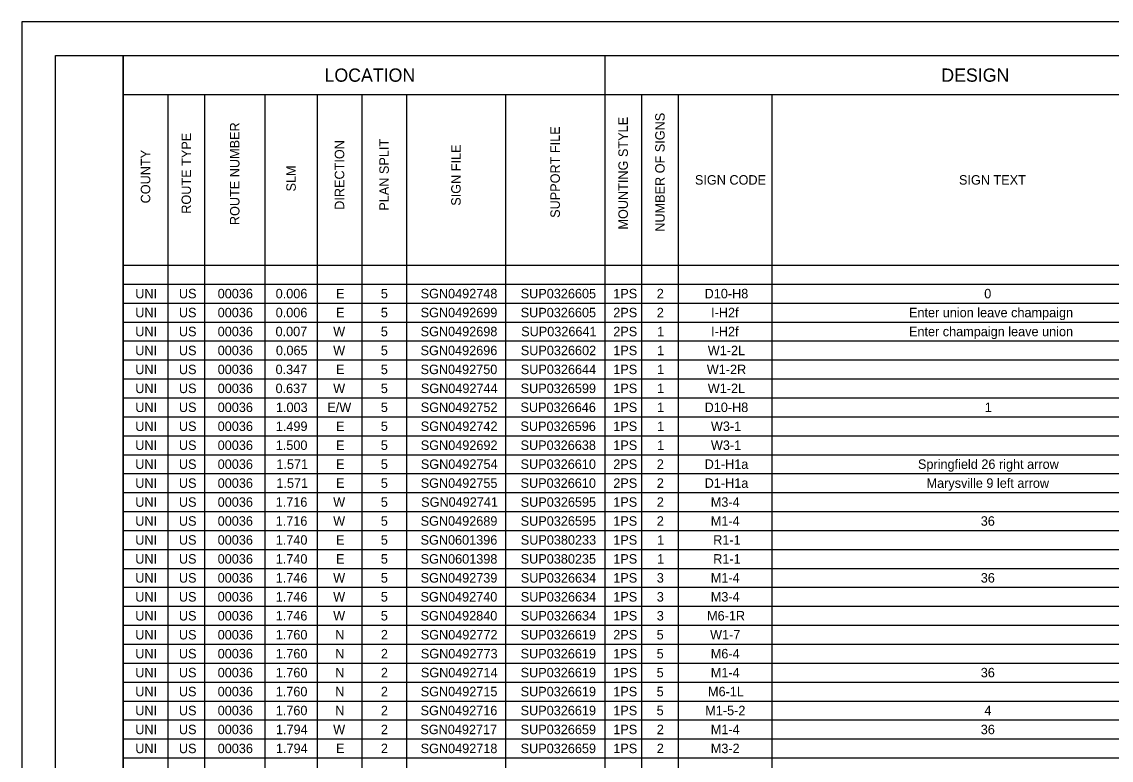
# Model space of a CAD drawing. Extents: x 0 to 34, y 0 to 22.
# Drawn here: x 0 to 16.1, y 11.09 to 22 of the extents above; entities that cross this region are included whole.
import ezdxf

# ---------------------------------------------------------------- set-up
doc = ezdxf.new("R2010")
doc.units = 0
for name, color, linetype in [('Default', 7, 'Continuous'), ('SH_Border', 7, 'Continuous'), ('SH_Cut_Line', 7, 'Continuous'), ('SH_Data', 7, 'Continuous')]:
    doc.layers.add(name, color=color, linetype=linetype)

msp = doc.modelspace()

# ---------------------------------------------------------------- linework, layer by layer
at = {"layer": 'SH_Border'}
for points in [[(0.5, 21.5), (1.5, 21.5), (1.5, 0.5), (0.5, 0.5)], [(1.5, 21.5), (33.5, 21.5), (33.5, 0.5), (1.5, 0.5)]]:
    msp.add_lwpolyline(points, close=True, dxfattribs=at)
at = {"layer": 'SH_Cut_Line'}
msp.add_lwpolyline([(0, 0), (34, 0), (34, 22), (0, 22)], close=True, dxfattribs=at)
at = {"layer": 'SH_Data'}
for p, q in [((1.5, 21.5), (32.004, 21.5)), ((8.615, 21.5), (8.615, 0.764)), ((1.5, 20.924), (28.232, 20.924)), ((1.5, 20.924), (1.5, 0.764)), ((2.159, 20.924), (2.159, 0.764)), ((2.702, 20.924), (2.702, 0.764)), ((3.592, 20.924), (3.592, 0.764)), ((4.366, 20.924), (4.366, 0.764)), ((5.025, 20.924), (5.025, 0.764)), ((5.684, 20.924), (5.684, 0.764)), ((7.149, 20.924), (7.149, 0.764)), ((9.159, 20.924), (9.159, 0.764)), ((9.702, 20.924), (9.702, 0.764)), ((11.086, 20.924), (11.086, 0.764)), ((1.5, 18.404), (32.004, 18.404)), ((1.5, 18.124), (32.004, 18.124)), ((1.5, 17.844), (32.004, 17.844)), ((1.5, 17.564), (32.004, 17.564)), ((1.5, 17.284), (32.004, 17.284)), ((1.5, 17.004), (32.004, 17.004)), ((1.5, 16.724), (32.004, 16.724)), ((1.5, 16.444), (32.004, 16.444)), ((1.5, 16.164), (32.004, 16.164)), ((1.5, 15.884), (32.004, 15.884)), ((1.5, 15.604), (32.004, 15.604)), ((1.5, 15.324), (32.004, 15.324)), ((1.5, 15.044), (32.004, 15.044)), ((1.5, 14.764), (32.004, 14.764)), ((1.5, 14.484), (32.004, 14.484)), ((1.5, 14.204), (32.004, 14.204)), ((1.5, 13.924), (32.004, 13.924)), ((1.5, 13.644), (32.004, 13.644)), ((1.5, 13.364), (32.004, 13.364)), ((1.5, 13.084), (32.004, 13.084)), ((1.5, 12.804), (32.004, 12.804)), ((1.5, 12.524), (32.004, 12.524)), ((1.5, 12.244), (32.004, 12.244)), ((1.5, 11.964), (32.004, 11.964)), ((1.5, 11.684), (32.004, 11.684)), ((1.5, 11.404), (32.004, 11.404)), ((1.5, 11.124), (32.004, 11.124))]:
    msp.add_line(p, q, dxfattribs=at)

# ---------------------------------------------------------------- texts
at = {"layer": 'Default'}
for s, height, p in [('LOCATION', 0.196, (4.474, 21.114)), ('DESIGN', 0.196, (13.589, 21.114)), ('SIGN CODE', 0.14, (9.948, 19.594)), ('SIGN TEXT', 0.14, (13.85, 19.594)), ('UNI', 0.14, (1.677, 17.914)), ('US', 0.14, (2.322, 17.914)), ('00036', 0.14, (2.895, 17.914)), ('0.006', 0.14, (3.752, 17.914)), ('E', 0.14, (4.645, 17.914)), ('5', 0.14, (5.306, 17.914)), ('SGN0492748', 0.14, (5.894, 17.914)), ('SUP0326605', 0.14, (7.373, 17.914)), ('1PS', 0.14, (8.741, 17.914)), ('2', 0.14, (9.384, 17.914)), ('D10-H8', 0.14, (10.091, 17.914)), ('0', 0.14, (14.223, 17.914)), ('UNI', 0.14, (1.677, 17.634)), ('US', 0.14, (2.322, 17.634)), ('00036', 0.14, (2.895, 17.634)), ('0.006', 0.14, (3.752, 17.634)), ('E', 0.14, (4.645, 17.634)), ('5', 0.14, (5.306, 17.634)), ('SGN0492699', 0.14, (5.894, 17.634)), ('SUP0326605', 0.14, (7.373, 17.634)), ('2PS', 0.14, (8.741, 17.634)), ('2', 0.14, (9.384, 17.634)), ('I-H2f', 0.14, (10.187, 17.634)), ('Enter union leave champaign', 0.14, (13.111, 17.634)), ('UNI', 0.14, (1.677, 17.354)), ('US', 0.14, (2.322, 17.354)), ('00036', 0.14, (2.895, 17.354)), ('0.007', 0.14, (3.75, 17.354)), ('W', 0.14, (4.602, 17.354)), ('5', 0.14, (5.306, 17.354)), ('SGN0492698', 0.14, (5.894, 17.354)), ('SUP0326641', 0.14, (7.38, 17.354)), ('2PS', 0.14, (8.741, 17.354)), ('1', 0.14, (9.389, 17.354)), ('I-H2f', 0.14, (10.187, 17.354)), ('Enter champaign leave union', 0.14, (13.111, 17.354)), ('UNI', 0.14, (1.677, 17.074)), ('US', 0.14, (2.322, 17.074)), ('00036', 0.14, (2.895, 17.074)), ('0.065', 0.14, (3.755, 17.074)), ('W', 0.14, (4.602, 17.074)), ('5', 0.14, (5.306, 17.074)), ('SGN0492696', 0.14, (5.893, 17.074)), ('SUP0326602', 0.14, (7.374, 17.074)), ('1PS', 0.14, (8.741, 17.074)), ('1', 0.14, (9.389, 17.074)), ('W1-2L', 0.14, (10.138, 17.074)), ('UNI', 0.14, (1.677, 16.794)), ('US', 0.14, (2.322, 16.794)), ('00036', 0.14, (2.895, 16.794)), ('0.347', 0.14, (3.75, 16.794)), ('E', 0.14, (4.645, 16.794)), ('5', 0.14, (5.306, 16.794)), ('SGN0492750', 0.14, (5.893, 16.794)), ('SUP0326644', 0.14, (7.374, 16.794)), ('1PS', 0.14, (8.741, 16.794)), ('1', 0.14, (9.389, 16.794)), ('W1-2R', 0.14, (10.123, 16.794)), ('UNI', 0.14, (1.677, 16.514)), ('US', 0.14, (2.322, 16.514)), ('00036', 0.14, (2.895, 16.514)), ('0.637', 0.14, (3.75, 16.514)), ('W', 0.14, (4.602, 16.514)), ('5', 0.14, (5.306, 16.514)), ('SGN0492744', 0.14, (5.897, 16.514)), ('SUP0326599', 0.14, (7.372, 16.514)), ('1PS', 0.14, (8.741, 16.514)), ('1', 0.14, (9.389, 16.514)), ('W1-2L', 0.14, (10.138, 16.514)), ('UNI', 0.14, (1.677, 16.234)), ('US', 0.14, (2.322, 16.234)), ('00036', 0.14, (2.895, 16.234)), ('1.003', 0.14, (3.756, 16.234)), ('E/W', 0.14, (4.515, 16.234)), ('5', 0.14, (5.306, 16.234)), ('SGN0492752', 0.14, (5.896, 16.234)), ('SUP0326646', 0.14, (7.37, 16.234)), ('1PS', 0.14, (8.741, 16.234)), ('1', 0.14, (9.389, 16.234)), ('D10-H8', 0.14, (10.091, 16.234)), ('1', 0.14, (14.232, 16.234)), ('UNI', 0.14, (1.677, 15.954)), ('US', 0.14, (2.322, 15.954)), ('00036', 0.14, (2.895, 15.954)), ('1.499', 0.14, (3.754, 15.954)), ('E', 0.14, (4.645, 15.954)), ('5', 0.14, (5.306, 15.954)), ('SGN0492742', 0.14, (5.896, 15.954)), ('SUP0326596', 0.14, (7.37, 15.954)), ('1PS', 0.14, (8.741, 15.954)), ('1', 0.14, (9.389, 15.954)), ('W3-1', 0.14, (10.184, 15.954)), ('UNI', 0.14, (1.677, 15.674)), ('US', 0.14, (2.322, 15.674)), ('00036', 0.14, (2.895, 15.674)), ('1.500', 0.14, (3.753, 15.674)), ('E', 0.14, (4.645, 15.674)), ('5', 0.14, (5.306, 15.674)), ('SGN0492692', 0.14, (5.896, 15.674)), ('SUP0326638', 0.14, (7.371, 15.674)), ('1PS', 0.14, (8.741, 15.674)), ('1', 0.14, (9.389, 15.674)), ('W3-1', 0.14, (10.184, 15.674)), ('UNI', 0.14, (1.677, 15.394)), ('US', 0.14, (2.322, 15.394)), ('00036', 0.14, (2.895, 15.394)), ('1.571', 0.14, (3.762, 15.394)), ('E', 0.14, (4.645, 15.394)), ('5', 0.14, (5.306, 15.394)), ('SGN0492754', 0.14, (5.897, 15.394)), ('SUP0326610', 0.14, (7.371, 15.394)), ('2PS', 0.14, (8.741, 15.394)), ('2', 0.14, (9.384, 15.394)), ('D1-H1a', 0.14, (10.092, 15.394)), ('Springfield 26 right arrow', 0.14, (13.244, 15.394)), ('UNI', 0.14, (1.677, 15.114)), ('US', 0.14, (2.322, 15.114)), ('00036', 0.14, (2.895, 15.114)), ('1.571', 0.14, (3.762, 15.114)), ('E', 0.14, (4.645, 15.114)), ('5', 0.14, (5.306, 15.114)), ('SGN0492755', 0.14, (5.895, 15.114)), ('SUP0326610', 0.14, (7.371, 15.114)), ('2PS', 0.14, (8.741, 15.114)), ('2', 0.14, (9.384, 15.114)), ('D1-H1a', 0.14, (10.092, 15.114)), ('Marysville 9 left arrow', 0.14, (13.371, 15.114)), ('UNI', 0.14, (1.677, 14.834)), ('US', 0.14, (2.322, 14.834)), ('00036', 0.14, (2.895, 14.834)), ('1.716', 0.14, (3.752, 14.834)), ('W', 0.14, (4.602, 14.834)), ('5', 0.14, (5.306, 14.834)), ('SGN0492741', 0.14, (5.902, 14.834)), ('SUP0326595', 0.14, (7.373, 14.834)), ('1PS', 0.14, (8.741, 14.834)), ('2', 0.14, (9.384, 14.834)), ('M3-4', 0.14, (10.182, 14.834)), ('UNI', 0.14, (1.677, 14.554)), ('US', 0.14, (2.322, 14.554)), ('00036', 0.14, (2.895, 14.554)), ('1.716', 0.14, (3.752, 14.554)), ('W', 0.14, (4.602, 14.554)), ('5', 0.14, (5.306, 14.554)), ('SGN0492689', 0.14, (5.894, 14.554)), ('SUP0326595', 0.14, (7.373, 14.554)), ('1PS', 0.14, (8.741, 14.554)), ('2', 0.14, (9.384, 14.554)), ('M1-4', 0.14, (10.182, 14.554)), ('36', 0.14, (14.172, 14.554)), ('UNI', 0.14, (1.677, 14.274)), ('US', 0.14, (2.322, 14.274)), ('00036', 0.14, (2.895, 14.274)), ('1.740', 0.14, (3.753, 14.274)), ('E', 0.14, (4.645, 14.274)), ('5', 0.14, (5.306, 14.274)), ('SGN0601396', 0.14, (5.893, 14.274)), ('SUP0380233', 0.14, (7.374, 14.274)), ('1PS', 0.14, (8.741, 14.274)), ('1', 0.14, (9.389, 14.274)), ('R1-1', 0.14, (10.218, 14.274)), ('UNI', 0.14, (1.677, 13.994)), ('US', 0.14, (2.322, 13.994)), ('00036', 0.14, (2.895, 13.994)), ('1.740', 0.14, (3.753, 13.994)), ('E', 0.14, (4.645, 13.994)), ('5', 0.14, (5.306, 13.994)), ('SGN0601398', 0.14, (5.894, 13.994)), ('SUP0380235', 0.14, (7.373, 13.994)), ('1PS', 0.14, (8.741, 13.994)), ('1', 0.14, (9.389, 13.994)), ('R1-1', 0.14, (10.218, 13.994)), ('UNI', 0.14, (1.677, 13.714)), ('US', 0.14, (2.322, 13.714)), ('00036', 0.14, (2.895, 13.714)), ('1.746', 0.14, (3.752, 13.714)), ('W', 0.14, (4.602, 13.714)), ('5', 0.14, (5.306, 13.714)), ('SGN0492739', 0.14, (5.894, 13.714)), ('SUP0326634', 0.14, (7.374, 13.714)), ('1PS', 0.14, (8.741, 13.714)), ('3', 0.14, (9.384, 13.714)), ('M1-4', 0.14, (10.182, 13.714)), ('36', 0.14, (14.172, 13.714)), ('UNI', 0.14, (1.677, 13.434)), ('US', 0.14, (2.322, 13.434)), ('00036', 0.14, (2.895, 13.434)), ('1.746', 0.14, (3.752, 13.434)), ('W', 0.14, (4.602, 13.434)), ('5', 0.14, (5.306, 13.434)), ('SGN0492740', 0.14, (5.893, 13.434)), ('SUP0326634', 0.14, (7.374, 13.434)), ('1PS', 0.14, (8.741, 13.434)), ('3', 0.14, (9.384, 13.434)), ('M3-4', 0.14, (10.182, 13.434)), ('UNI', 0.14, (1.677, 13.154)), ('US', 0.14, (2.322, 13.154)), ('00036', 0.14, (2.895, 13.154)), ('1.746', 0.14, (3.752, 13.154)), ('W', 0.14, (4.602, 13.154)), ('5', 0.14, (5.306, 13.154)), ('SGN0492840', 0.14, (5.893, 13.154)), ('SUP0326634', 0.14, (7.374, 13.154)), ('1PS', 0.14, (8.741, 13.154)), ('3', 0.14, (9.384, 13.154)), ('M6-1R', 0.14, (10.127, 13.154)), ('UNI', 0.14, (1.677, 12.874)), ('US', 0.14, (2.322, 12.874)), ('00036', 0.14, (2.895, 12.874)), ('1.760', 0.14, (3.753, 12.874)), ('N', 0.14, (4.632, 12.874)), ('2', 0.14, (5.307, 12.874)), ('SGN0492772', 0.14, (5.896, 12.874)), ('SUP0326619', 0.14, (7.372, 12.874)), ('2PS', 0.14, (8.741, 12.874)), ('5', 0.14, (9.382, 12.874)), ('W1-7', 0.14, (10.172, 12.874)), ('UNI', 0.14, (1.677, 12.594)), ('US', 0.14, (2.322, 12.594)), ('00036', 0.14, (2.895, 12.594)), ('1.760', 0.14, (3.753, 12.594)), ('N', 0.14, (4.632, 12.594)), ('2', 0.14, (5.307, 12.594)), ('SGN0492773', 0.14, (5.897, 12.594)), ('SUP0326619', 0.14, (7.372, 12.594)), ('1PS', 0.14, (8.741, 12.594)), ('5', 0.14, (9.382, 12.594)), ('M6-4', 0.14, (10.182, 12.594)), ('UNI', 0.14, (1.677, 12.314)), ('US', 0.14, (2.322, 12.314)), ('00036', 0.14, (2.895, 12.314)), ('1.760', 0.14, (3.753, 12.314)), ('N', 0.14, (4.632, 12.314)), ('2', 0.14, (5.307, 12.314)), ('SGN0492714', 0.14, (5.897, 12.314)), ('SUP0326619', 0.14, (7.372, 12.314)), ('1PS', 0.14, (8.741, 12.314)), ('5', 0.14, (9.382, 12.314)), ('M1-4', 0.14, (10.182, 12.314)), ('36', 0.14, (14.172, 12.314)), ('UNI', 0.14, (1.677, 12.034)), ('US', 0.14, (2.322, 12.034)), ('00036', 0.14, (2.895, 12.034)), ('1.760', 0.14, (3.753, 12.034)), ('N', 0.14, (4.632, 12.034)), ('2', 0.14, (5.307, 12.034)), ('SGN0492715', 0.14, (5.895, 12.034)), ('SUP0326619', 0.14, (7.372, 12.034)), ('1PS', 0.14, (8.741, 12.034)), ('5', 0.14, (9.382, 12.034)), ('M6-1L', 0.14, (10.141, 12.034)), ('UNI', 0.14, (1.677, 11.754)), ('US', 0.14, (2.322, 11.754)), ('00036', 0.14, (2.895, 11.754)), ('1.760', 0.14, (3.753, 11.754)), ('N', 0.14, (4.632, 11.754)), ('2', 0.14, (5.307, 11.754)), ('SGN0492716', 0.14, (5.893, 11.754)), ('SUP0326619', 0.14, (7.372, 11.754)), ('1PS', 0.14, (8.741, 11.754)), ('5', 0.14, (9.382, 11.754)), ('M1-5-2', 0.14, (10.101, 11.754)), ('4', 0.14, (14.226, 11.754)), ('UNI', 0.14, (1.677, 11.474)), ('US', 0.14, (2.322, 11.474)), ('00036', 0.14, (2.895, 11.474)), ('1.794', 0.14, (3.756, 11.474)), ('W', 0.14, (4.602, 11.474)), ('2', 0.14, (5.307, 11.474)), ('SGN0492717', 0.14, (5.89, 11.474)), ('SUP0326659', 0.14, (7.372, 11.474)), ('1PS', 0.14, (8.741, 11.474)), ('2', 0.14, (9.384, 11.474)), ('M1-4', 0.14, (10.182, 11.474)), ('36', 0.14, (14.172, 11.474)), ('UNI', 0.14, (1.677, 11.194)), ('US', 0.14, (2.322, 11.194)), ('00036', 0.14, (2.895, 11.194)), ('1.794', 0.14, (3.756, 11.194)), ('E', 0.14, (4.645, 11.194)), ('2', 0.14, (5.307, 11.194)), ('SGN0492718', 0.14, (5.894, 11.194)), ('SUP0326659', 0.14, (7.372, 11.194)), ('1PS', 0.14, (8.741, 11.194)), ('2', 0.14, (9.384, 11.194)), ('M3-2', 0.14, (10.182, 11.194))]:
    msp.add_text(s, height=height, dxfattribs=at).set_placement(p)
for s, p in [('NUMBER OF SIGNS', (9.501, 18.898)), ('ROUTE NUMBER', (3.217, 18.996)), ('SUPPORT FILE', (7.952, 19.103)), ('MOUNTING STYLE', (8.957, 18.93)), ('ROUTE TYPE', (2.501, 19.164)), ('DIRECTION', (4.765, 19.222)), ('PLAN SPLIT', (5.424, 19.209)), ('SIGN FILE', (6.486, 19.282)), ('COUNTY', (1.899, 19.317)), ('SLM', (4.049, 19.493))]:
    msp.add_text(s, height=0.14, rotation=90, dxfattribs=at).set_placement(p)

doc.saveas('drawing.dxf')
